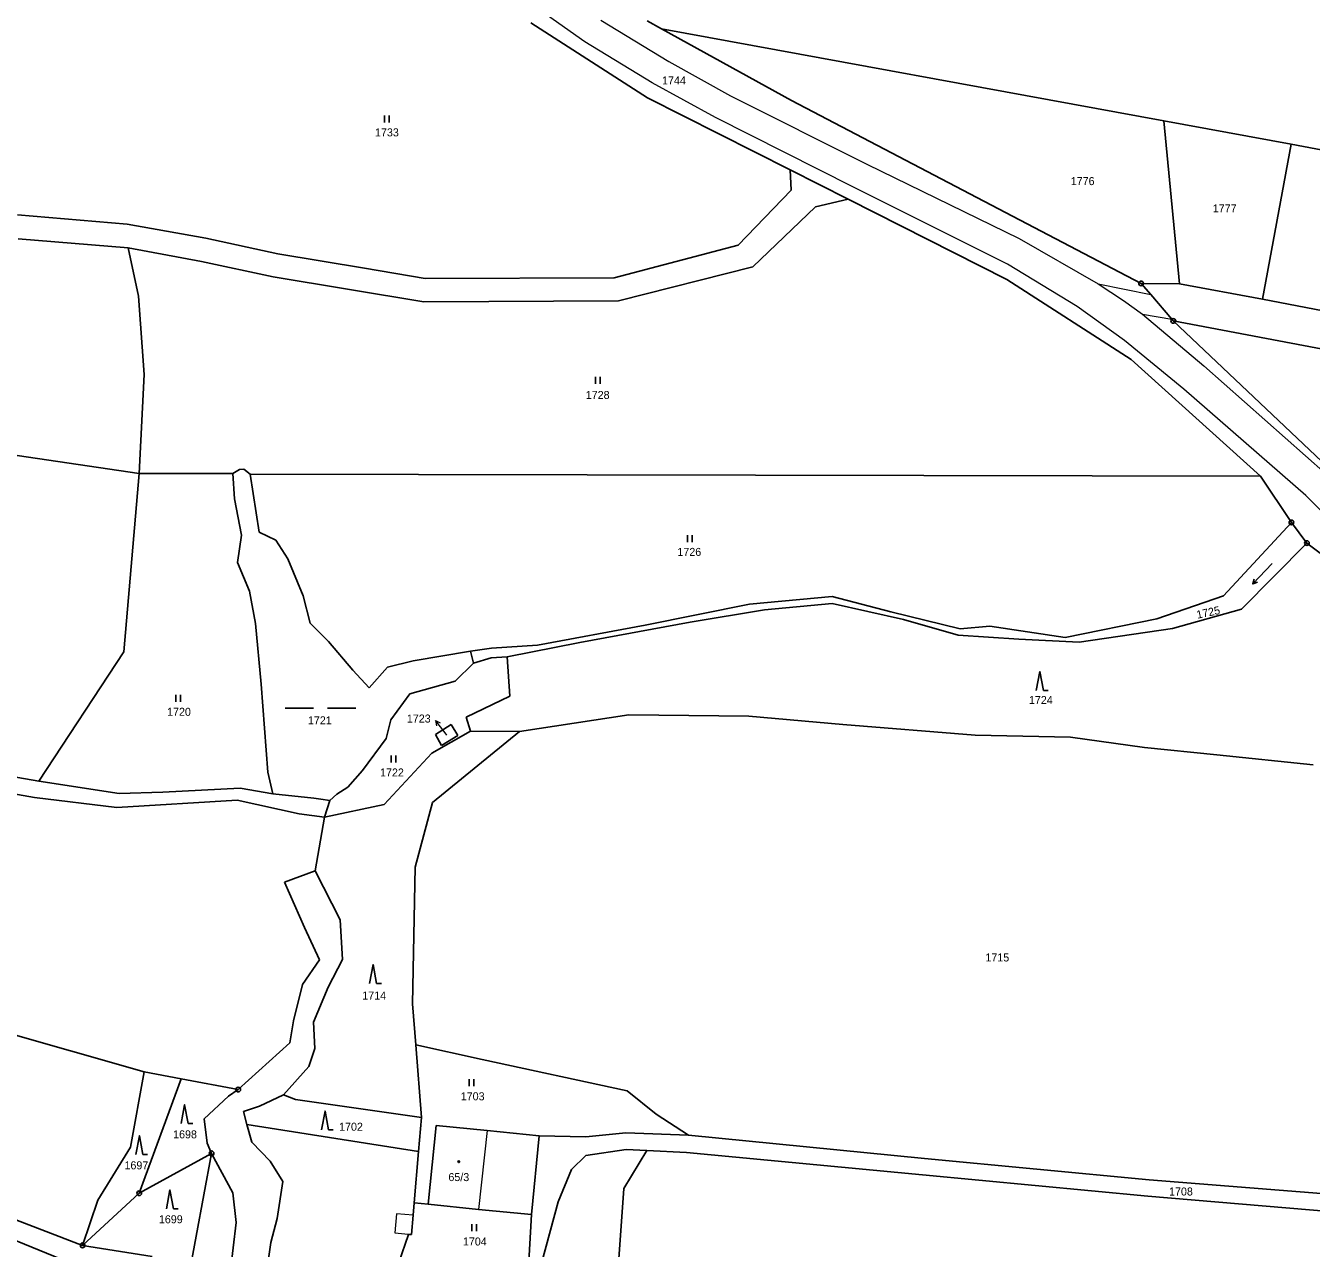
# Model space of a CAD drawing. Extents: x -601131 to -597152, y -1058536 to -1055911.
# Drawn here: x -599066.3 to -598793.2, y -1057555.3 to -1057295.7 of the extents above; entities that cross this region are included whole.
import ezdxf
from ezdxf.enums import TextEntityAlignment as Align

# ---------------------------------------------------------------- set-up
doc = ezdxf.new("R2010")
doc.units = 0
doc.header["$LTSCALE"] = 0.68
for name, color, linetype, lineweight in [('1', 7, 'Continuous', 25), ('3', 7, 'Continuous', 25), ('4', 7, 'Continuous', 13), ('5', 7, 'Continuous', 25), ('7', 7, 'Continuous', 13), ('8', 7, 'Continuous', 25)]:
    doc.layers.add(name, color=color, linetype=linetype, lineweight=lineweight)
doc.layers.add('2', color=7, linetype='Continuous')

msp = doc.modelspace()

# ---------------------------------------------------------------- linework, layer by layer
at = {"layer": '1'}
for p, q in [((-598958.96, -1057295.03), (-598934.21, -1057310.98)), ((-598934.26, -1057294.62), (-598931.22, -1057296.3)), ((-598903.62, -1057311.52), (-598931.22, -1057296.3)), ((-598931.22, -1057296.3), (-598824.56, -1057315.9)), ((-598934.21, -1057310.98), (-598903.88, -1057326.31)), ((-598829.39, -1057350.39), (-598903.62, -1057311.52)), ((-598824.56, -1057315.9), (-598821.25, -1057350.48)), ((-598797.52, -1057320.86), (-598824.56, -1057315.9)), ((-598803.57, -1057353.78), (-598797.52, -1057320.86)), ((-598797.52, -1057320.86), (-598728.5, -1057333.56)), ((-598891.58, -1057332.53), (-598903.88, -1057326.31)), ((-598903.88, -1057326.31), (-598903.71, -1057330.63)), ((-598903.71, -1057330.63), (-598914.96, -1057342.25)), ((-598898.55, -1057334.13), (-598891.58, -1057332.53)), ((-598857.89, -1057349.56), (-598891.58, -1057332.53)), ((-599044.73, -1057337.81), (-599067.99, -1057335.85)), ((-598911.87, -1057346.88), (-598898.55, -1057334.13)), ((-599027.99, -1057340.81), (-599044.73, -1057337.81)), ((-599044.53, -1057342.86), (-599067.87, -1057340.91)), ((-599012.72, -1057344.12), (-599027.99, -1057340.81)), ((-599042.32, -1057353.14), (-599044.53, -1057342.86)), ((-599044.53, -1057342.86), (-599028.92, -1057345.72)), ((-598994.28, -1057347.17), (-599012.72, -1057344.12)), ((-598914.96, -1057342.25), (-598941.26, -1057349.21)), ((-599028.92, -1057345.72), (-599013.73, -1057349.02)), ((-598981.46, -1057349.34), (-598994.28, -1057347.17)), ((-598940.39, -1057354.13), (-598911.87, -1057346.88)), ((-599013.73, -1057349.02), (-598981.74, -1057354.33)), ((-598941.26, -1057349.21), (-598981.46, -1057349.34)), ((-598831.5, -1057366.59), (-598857.89, -1057349.56)), ((-598829.39, -1057350.39), (-598827.34, -1057352.78)), ((-598821.25, -1057350.48), (-598829.39, -1057350.39)), ((-598827.34, -1057352.78), (-598822.88, -1057357.98)), ((-598821.25, -1057350.48), (-598803.57, -1057353.78)), ((-599041.11, -1057369.78), (-599042.32, -1057353.14)), ((-598981.74, -1057354.33), (-598940.39, -1057354.13)), ((-598776.33, -1057358.95), (-598803.57, -1057353.78)), ((-598822.88, -1057357.98), (-598822.53, -1057358.38)), ((-598822.53, -1057358.38), (-598786.08, -1057392.93)), ((-598822.53, -1057358.38), (-598777.57, -1057366.85)), ((-598804.05, -1057391.35), (-598831.5, -1057366.59)), ((-599042.15, -1057390.77), (-599041.11, -1057369.78)), ((-599102.38, -1057381.87), (-599042.15, -1057390.77)), ((-599042.15, -1057390.77), (-599045.4, -1057428.67)), ((-599042.15, -1057390.77), (-599022.25, -1057390.8)), ((-599022.25, -1057390.8), (-599020.88, -1057389.94)), ((-599022.25, -1057390.8), (-599021.94, -1057396.14)), ((-599020.88, -1057389.94), (-599019.96, -1057389.84)), ((-599019.96, -1057389.84), (-599018.56, -1057390.9)), ((-599018.56, -1057390.9), (-598911.3, -1057391.12)), ((-599018.56, -1057390.9), (-599016.68, -1057403.25)), ((-598911.3, -1057391.12), (-598804.05, -1057391.35)), ((-598797.45, -1057401.16), (-598804.05, -1057391.35)), ((-599021.94, -1057396.14), (-599020.4, -1057403.88)), ((-598811.9, -1057416.78), (-598797.45, -1057401.16)), ((-598797.45, -1057401.16), (-598794.16, -1057405.55)), ((-599020.4, -1057403.88), (-599021.31, -1057409.66)), ((-599016.68, -1057403.25), (-599013.11, -1057404.96)), ((-599013.11, -1057404.96), (-599010.56, -1057408.92)), ((-598794.16, -1057405.55), (-598808.05, -1057419.59)), ((-598794.16, -1057405.55), (-598776.39, -1057419)), ((-599021.31, -1057409.66), (-599018.76, -1057415.78)), ((-599010.56, -1057408.92), (-599007.33, -1057416.74)), ((-599018.76, -1057415.78), (-599017.43, -1057422.64)), ((-599007.33, -1057416.74), (-599005.86, -1057422.57)), ((-598912.54, -1057418.54), (-598895.02, -1057416.93)), ((-598895.01, -1057418.42), (-598909.38, -1057419.76)), ((-598895.02, -1057416.93), (-598882.51, -1057420.19)), ((-598879.82, -1057421.82), (-598895.01, -1057418.42)), ((-598826.05, -1057421.64), (-598811.9, -1057416.78)), ((-598934.67, -1057423.02), (-598912.54, -1057418.54)), ((-598909.38, -1057419.76), (-598925.18, -1057422.35)), ((-598882.51, -1057420.19), (-598867.77, -1057423.78)), ((-598808.05, -1057419.59), (-598822.74, -1057423.71)), ((-599017.43, -1057422.64), (-599016.26, -1057435.52)), ((-599005.86, -1057422.57), (-599001.98, -1057426.44)), ((-598957.56, -1057427.27), (-598934.67, -1057423.02)), ((-598925.18, -1057422.35), (-598948.55, -1057426.7)), ((-598868.26, -1057425.14), (-598879.82, -1057421.82)), ((-598867.77, -1057423.78), (-598861.48, -1057423.22)), ((-598861.48, -1057423.22), (-598845.53, -1057425.62)), ((-598845.53, -1057425.62), (-598826.05, -1057421.64)), ((-598822.74, -1057423.71), (-598842.51, -1057426.59)), ((-599001.98, -1057426.44), (-598996.78, -1057432.54)), ((-598948.55, -1057426.7), (-598963.98, -1057429.75)), ((-598855.35, -1057425.93), (-598868.26, -1057425.14)), ((-598842.51, -1057426.59), (-598855.35, -1057425.93)), ((-599045.4, -1057428.67), (-599063.5, -1057456.12)), ((-598984, -1057430.57), (-598971.79, -1057428.51)), ((-598971.79, -1057428.51), (-598967.32, -1057427.85)), ((-598971.14, -1057431.04), (-598971.79, -1057428.51)), ((-598967.32, -1057427.85), (-598957.56, -1057427.27)), ((-598993.32, -1057436.3), (-598989.42, -1057431.94)), ((-598989.42, -1057431.94), (-598984, -1057430.57)), ((-598975.03, -1057434.88), (-598971.14, -1057431.04)), ((-598967.42, -1057429.95), (-598971.14, -1057431.04)), ((-598963.98, -1057429.75), (-598967.42, -1057429.95)), ((-598963.98, -1057429.75), (-598963.42, -1057438.07)), ((-598996.78, -1057432.54), (-598993.32, -1057436.3)), ((-598984.7, -1057437.55), (-598975.03, -1057434.88)), ((-599016.26, -1057435.52), (-599014.87, -1057454.19)), ((-598988.75, -1057443.12), (-598984.7, -1057437.55)), ((-598963.42, -1057438.07), (-598972.71, -1057442.5)), ((-598972.71, -1057442.5), (-598971.81, -1057445.54)), ((-598938.15, -1057442.03), (-598961.38, -1057445.6)), ((-598912.67, -1057442.35), (-598938.15, -1057442.03)), ((-598892.75, -1057444.07), (-598912.67, -1057442.35)), ((-598989.7, -1057447.07), (-598988.75, -1057443.12)), ((-598971.81, -1057445.54), (-598980.03, -1057450.18)), ((-598961.38, -1057445.6), (-598979.85, -1057460.63)), ((-598979.26, -1057446.18), (-598975.9, -1057444.1)), ((-598975.9, -1057444.1), (-598974.51, -1057446.45)), ((-598971.81, -1057445.54), (-598961.38, -1057445.6)), ((-598864.65, -1057446.36), (-598892.75, -1057444.07)), ((-598994.72, -1057453.89), (-598989.7, -1057447.07)), ((-598977.94, -1057448.52), (-598979.26, -1057446.18)), ((-598974.51, -1057446.45), (-598977.94, -1057448.52)), ((-598844.38, -1057446.77), (-598864.65, -1057446.36)), ((-598828.64, -1057449), (-598844.38, -1057446.77)), ((-599127.83, -1057448.58), (-599064.38, -1057459.58)), ((-599063.5, -1057456.12), (-599093.62, -1057450.91)), ((-598980.03, -1057450.18), (-598990.15, -1057461.08)), ((-598813.26, -1057450.51), (-598828.64, -1057449)), ((-598792.8, -1057452.65), (-598813.26, -1057450.51)), ((-598997.85, -1057457.4), (-598994.72, -1057453.89)), ((-599046.42, -1057458.74), (-599063.5, -1057456.12)), ((-599014.87, -1057454.19), (-599013.77, -1057458.79)), ((-599037.17, -1057458.46), (-599046.42, -1057458.74)), ((-599020.71, -1057457.64), (-599037.17, -1057458.46)), ((-599013.77, -1057458.79), (-599020.71, -1057457.64)), ((-599005.1, -1057459.73), (-599013.77, -1057458.79)), ((-599001.67, -1057460.26), (-599000.21, -1057458.88)), ((-599000.21, -1057458.88), (-598997.85, -1057457.4)), ((-599064.38, -1057459.58), (-599046.92, -1057461.73)), ((-599046.92, -1057461.73), (-599021.39, -1057460.19)), ((-599021.39, -1057460.19), (-599008.19, -1057463.09)), ((-599003.59, -1057459.95), (-599005.1, -1057459.73)), ((-599001.67, -1057460.26), (-599003.59, -1057459.95)), ((-599002.81, -1057463.74), (-599001.67, -1057460.26)), ((-598990.15, -1057461.08), (-599002.81, -1057463.74)), ((-598979.85, -1057460.63), (-598983.55, -1057474.36)), ((-599008.19, -1057463.09), (-599002.81, -1057463.74)), ((-599004.8, -1057475.2), (-599002.81, -1057463.74)), ((-599004.8, -1057475.2), (-599011.29, -1057477.61)), ((-598999.51, -1057485.56), (-599004.8, -1057475.2)), ((-598983.55, -1057474.36), (-598984.11, -1057503.41)), ((-599011.29, -1057477.61), (-599007.03, -1057487.24)), ((-598999.01, -1057493.99), (-598999.51, -1057485.56)), ((-599041.08, -1057517.85), (-599144.3, -1057488.64)), ((-599007.03, -1057487.24), (-599003.85, -1057494.08)), ((-599003.85, -1057494.08), (-599007.49, -1057499.31)), ((-599002.01, -1057499.85), (-598999.01, -1057493.99)), ((-599007.49, -1057499.31), (-599009.42, -1057507.01)), ((-599005.12, -1057507.31), (-599002.01, -1057499.85)), ((-598984.11, -1057503.41), (-598983.44, -1057512.14)), ((-599009.42, -1057507.01), (-599010.18, -1057511.73)), ((-599004.87, -1057512.9), (-599005.12, -1057507.31)), ((-599010.18, -1057511.73), (-599021.13, -1057521.62)), ((-599006.15, -1057516.71), (-599004.87, -1057512.9)), ((-598983.44, -1057512.14), (-598982.24, -1057527.57)), ((-598983.44, -1057512.14), (-598969.33, -1057515.21)), ((-599011.5, -1057522.74), (-599006.15, -1057516.71)), ((-598969.33, -1057515.21), (-598938.51, -1057521.93)), ((-599044.01, -1057533.87), (-599041.08, -1057517.85)), ((-599033.23, -1057519.33), (-599042.16, -1057543.65)), ((-599041.08, -1057517.85), (-599033.23, -1057519.33)), ((-599021.13, -1057521.62), (-599033.23, -1057519.33)), ((-599023.21, -1057523.05), (-599021.13, -1057521.62)), ((-598938.51, -1057521.93), (-598932.36, -1057526.85)), ((-599028.39, -1057527.82), (-599023.21, -1057523.05)), ((-599011.5, -1057522.74), (-599016.58, -1057525.15)), ((-599008.96, -1057523.72), (-599011.5, -1057522.74)), ((-598982.24, -1057527.57), (-599008.96, -1057523.72)), ((-599016.58, -1057525.15), (-599020.04, -1057526.31)), ((-599020.04, -1057526.31), (-599019.28, -1057529.04)), ((-598982.84, -1057534.8), (-598982.24, -1057527.57)), ((-598932.36, -1057526.85), (-598925.51, -1057531.35)), ((-599027.72, -1057533.03), (-599028.39, -1057527.82)), ((-599019.28, -1057529.04), (-598982.84, -1057534.8)), ((-599018.24, -1057532.8), (-599019.28, -1057529.04)), ((-598980.79, -1057545.98), (-598979.08, -1057529.28)), ((-598979.08, -1057529.28), (-598968.25, -1057530.35)), ((-598968.25, -1057530.35), (-598957.22, -1057531.47)), ((-599026.8, -1057535.18), (-599027.72, -1057533.03)), ((-599014.37, -1057536.81), (-599018.24, -1057532.8)), ((-598957.22, -1057531.47), (-598958.81, -1057548.18)), ((-598947.32, -1057531.66), (-598957.22, -1057531.47)), ((-598938.79, -1057530.83), (-598947.32, -1057531.66)), ((-598925.51, -1057531.35), (-598938.79, -1057530.83)), ((-598925.51, -1057531.35), (-598875.41, -1057536.28)), ((-599050.98, -1057545.14), (-599044.01, -1057533.87)), ((-599042.16, -1057543.65), (-599026.8, -1057535.18)), ((-599026.8, -1057535.18), (-599034.74, -1057578.08)), ((-599022.25, -1057543.56), (-599026.8, -1057535.18)), ((-598983.74, -1057545.67), (-598982.84, -1057534.8)), ((-598950.37, -1057538.64), (-598947.3, -1057535.63)), ((-598947.3, -1057535.63), (-598938.76, -1057534.33)), ((-598934.32, -1057534.57), (-598939.22, -1057542.65)), ((-598938.76, -1057534.33), (-598934.32, -1057534.57)), ((-598925.93, -1057535.01), (-598934.32, -1057534.57)), ((-598875.82, -1057539.76), (-598925.93, -1057535.01)), ((-599011.67, -1057541.18), (-599014.37, -1057536.81)), ((-598953.21, -1057545.5), (-598950.37, -1057538.64)), ((-598875.41, -1057536.28), (-598827.66, -1057540.77)), ((-599012.83, -1057548.99), (-599011.67, -1057541.18)), ((-598827.94, -1057544.26), (-598875.82, -1057539.76)), ((-598827.66, -1057540.77), (-598789.35, -1057543.88)), ((-599054.2, -1057554.72), (-599042.16, -1057543.65)), ((-599021.57, -1057549.87), (-599022.25, -1057543.56)), ((-598939.22, -1057542.65), (-598944.53, -1057616.7)), ((-599074.8, -1057546.82), (-599054.2, -1057554.72)), ((-599054.2, -1057554.72), (-599050.98, -1057545.14)), ((-598983.96, -1057548.34), (-598983.74, -1057545.67)), ((-598980.79, -1057545.98), (-598983.74, -1057545.67)), ((-598970.08, -1057547.1), (-598980.79, -1057545.98)), ((-598956.67, -1057558.3), (-598953.21, -1057545.5)), ((-598788.59, -1057547.59), (-598827.94, -1057544.26)), ((-599014.22, -1057554.11), (-599012.83, -1057548.99)), ((-598983.96, -1057548.34), (-598984.33, -1057552.42)), ((-598958.81, -1057548.18), (-598970.08, -1057547.1)), ((-598959.43, -1057558.14), (-598958.81, -1057548.18)), ((-599054.42, -1057559.4), (-599075.83, -1057550.69)), ((-599022.86, -1057560.63), (-599021.57, -1057549.87)), ((-599039.4, -1057557.11), (-599054.2, -1057554.72)), ((-599016.78, -1057572.82), (-599014.22, -1057554.11)), ((-598987.03, -1057558.37), (-598984.98, -1057552.45)), ((-598984.98, -1057552.45), (-598984.33, -1057552.42))]:
    msp.add_line(p, q, dxfattribs=at)
at = {"layer": '3'}
for p, q in [((-598990.071, -1057316.23), (-598990.071, -1057314.73)), ((-598989.07, -1057316.23), (-598989.07, -1057314.73)), ((-598945.231, -1057371.76), (-598945.231, -1057370.26)), ((-598944.23, -1057371.76), (-598944.23, -1057370.26)), ((-598925.721, -1057405.34), (-598925.721, -1057403.84)), ((-598924.72, -1057405.34), (-598924.72, -1057403.84)), ((-598805.672, -1057414.244), (-598805.354, -1057413.193)), ((-598850.13, -1057436.85), (-598849.134, -1057436.85)), ((-599034.411, -1057439.3), (-599034.411, -1057437.8)), ((-599033.41, -1057439.3), (-599033.41, -1057437.8)), ((-599011.149, -1057440.59), (-599005.149, -1057440.59)), ((-599002.149, -1057440.59), (-598996.149, -1057440.59)), ((-598988.641, -1057452.14), (-598988.641, -1057450.64)), ((-598987.64, -1057452.14), (-598987.64, -1057450.64)), ((-598991.73, -1057499.07), (-598990.734, -1057499.07)), ((-598972.101, -1057520.93), (-598972.101, -1057519.43)), ((-598971.1, -1057520.93), (-598971.1, -1057519.43)), ((-599031.78, -1057528.85), (-599030.784, -1057528.85)), ((-599001.94, -1057530.19), (-599000.944, -1057530.19)), ((-599041.38, -1057535.44), (-599040.384, -1057535.44)), ((-599034.89, -1057546.95), (-599033.894, -1057546.95)), ((-598971.501, -1057551.7), (-598971.501, -1057550.2)), ((-598970.5, -1057551.7), (-598970.5, -1057550.2))]:
    msp.add_line(p, q, dxfattribs=at)
for points in [[(-598801.504, -1057409.928), (-598805.672, -1057414.244), (-598804.633, -1057413.89)], [(-598850.13, -1057436.85), (-598850.88, -1057432.85), (-598851.63, -1057436.85)], [(-598991.73, -1057499.07), (-598992.48, -1057495.07), (-598993.23, -1057499.07)], [(-599031.78, -1057528.85), (-599032.53, -1057524.85), (-599033.28, -1057528.85)], [(-599001.94, -1057530.19), (-599002.69, -1057526.19), (-599003.44, -1057530.19)], [(-599041.38, -1057535.44), (-599042.13, -1057531.44), (-599042.88, -1057535.44)], [(-599034.89, -1057546.95), (-599035.64, -1057542.95), (-599036.39, -1057546.95)]]:
    msp.add_lwpolyline(points, dxfattribs=at)
at = {"layer": '4'}
for p, q in [((-598947.49, -1057299.1), (-598956.65, -1057292.65)), ((-598944.12, -1057294.47), (-598929.71, -1057303.25)), ((-598933.22, -1057307.81), (-598947.49, -1057299.1)), ((-598929.71, -1057303.25), (-598916.61, -1057310.53)), ((-598919.8, -1057315.13), (-598933.22, -1057307.81)), ((-598916.61, -1057310.53), (-598887.65, -1057325.09)), ((-598890.48, -1057329.97), (-598919.8, -1057315.13)), ((-598887.65, -1057325.09), (-598855.24, -1057340.86)), ((-598857.78, -1057346.32), (-598890.48, -1057329.97)), ((-598855.24, -1057340.86), (-598838.49, -1057350.52)), ((-598842.93, -1057355.28), (-598857.78, -1057346.32)), ((-598838.49, -1057350.52), (-598833.08, -1057354)), ((-598838.49, -1057350.52), (-598827.34, -1057352.78)), ((-598832.93, -1057362.54), (-598842.93, -1057355.28)), ((-598833.08, -1057354), (-598829.09, -1057356.94)), ((-598829.09, -1057356.94), (-598816.06, -1057367.91)), ((-598829.09, -1057356.94), (-598822.88, -1057357.98)), ((-598820.28, -1057372.87), (-598832.93, -1057362.54)), ((-598816.06, -1057367.91), (-598790.12, -1057390.82)), ((-598794.42, -1057395.47), (-598820.28, -1057372.87)), ((-598786.47, -1057403.5), (-598794.42, -1057395.47)), ((-598968.25, -1057530.35), (-598970.08, -1057547.1)), ((-598987.52, -1057548.02), (-598987.89, -1057552.09)), ((-598983.96, -1057548.34), (-598987.52, -1057548.02)), ((-598987.89, -1057552.09), (-598984.33, -1057552.42))]:
    msp.add_line(p, q, dxfattribs=at)
at = {"layer": '5'}
msp.add_circle((-598974.2868, -1057536.9492), 0.175, dxfattribs=at)
at = {"layer": '7'}
msp.add_line((-598979.258, -1057443.245), (-598979.036, -1057444.343), dxfattribs=at)
msp.add_lwpolyline([(-598976.82, -1057446.38), (-598977.41, -1057445.61), (-598979.258, -1057443.245), (-598978.246, -1057443.726)], dxfattribs=at)
at = {"layer": '8'}
for centre, radius in [((-598829.39, -1057350.3899), 0.5), ((-598829.39, -1057350.3899), 0.0303), ((-598822.53, -1057358.3799), 0.5), ((-598822.53, -1057358.3799), 0.0303), ((-598797.45, -1057401.1599), 0.5), ((-598797.45, -1057401.1599), 0.0303), ((-598794.16, -1057405.5499), 0.5), ((-598794.16, -1057405.5499), 0.0303), ((-599021.13, -1057521.6199), 0.5), ((-599021.13, -1057521.6199), 0.0303), ((-599026.8, -1057535.1799), 0.5), ((-599026.8, -1057535.1799), 0.0303), ((-599042.16, -1057543.6499), 0.5), ((-599042.16, -1057543.6499), 0.0303), ((-599054.2, -1057554.7199), 0.5), ((-599054.2, -1057554.7199), 0.0303)]:
    msp.add_circle(centre, radius, dxfattribs=at)

# ---------------------------------------------------------------- texts
at = {"layer": '2'}
for s, p in [('1744', (-598928.59, -1057308.152)), ('1733', (-598989.55, -1057319.172)), ('1776', (-598841.79, -1057329.522)), ('1777', (-598811.62, -1057335.302)), ('1728', (-598944.79, -1057374.942)), ('1726', (-598925.33, -1057408.282)), ('1724', (-598850.67, -1057439.742)), ('1720', (-599033.71, -1057442.242)), ('1721', (-599003.8, -1057444.062)), ('1722', (-598988.48, -1057455.132)), ('1715', (-598859.91, -1057494.422)), ('1714', (-598992.25, -1057502.502)), ('1703', (-598971.34, -1057523.912)), ('1698', (-599032.43, -1057531.992)), ('1702', (-598997.18, -1057530.372)), ('1697', (-599042.76, -1057538.572)), ('65/3', (-598974.279, -1057541.072)), ('1708', (-598820.91, -1057544.132)), ('1699', (-599035.45, -1057550.032)), ('1704', (-598970.88, -1057554.752))]:
    msp.add_text(s, height=1.7, dxfattribs=at).set_placement(p, align=Align.CENTER)
msp.add_text('1725', height=1.7, rotation=12, dxfattribs=at).set_placement((-598814.9327, -1057421.1046), align=Align.CENTER)
msp.add_text('1723', height=1.7, dxfattribs=at).set_placement((-598980.26, -1057443.675), align=Align.RIGHT)

doc.saveas('drawing.dxf')
